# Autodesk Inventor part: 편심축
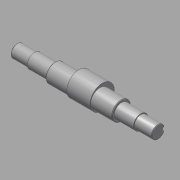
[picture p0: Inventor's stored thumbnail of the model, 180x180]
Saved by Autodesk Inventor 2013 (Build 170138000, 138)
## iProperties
Created: 2015-10
Part Number: 편심축
Document SubType Name: Modeling
Designer: mdu
Density: 1 g/cm^3
Material: 강철, 연강
Mass: 168.947 g
Surface Area: 248.524 cm^2
Volume: 168.947 cm^3
Author: mdu
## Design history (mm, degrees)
sketch "스케치1"
  geometry: L1 (-20.5, -41.331)-(-20.5, 32.669) reference; L2 (7.5, -30.031)-(7.5, 21.369) reference; L3 (135.5, -30.331)-(135.5, 21.669) reference; L4 (121.5, 21.369)-(121.5, -30.031) reference; L5 (184.5, -4.331)-(-57.5, -4.331); L6 (184.5, -4.331)-(184.5, 6.669); L7 (154.5, 8.169)-(121.5, 8.169); L8 (121.5, 8.169)-(121.5, 11.669); L9 (121.5, 11.669)-(7.5, 11.669); L10 (7.5, 11.669)-(7.5, 8.169); L11 (7.5, 8.169)-(-27.5, 8.169); L12 (-27.5, 8.169)-(-27.5, 6.669); L13 (-27.5, 6.669)-(-57.5, 6.669); L14 (-57.5, 6.669)-(-57.5, -4.331); L15 (154.5, 8.169)-(154.5, 6.669); L16 (154.5, 6.669)-(184.5, 6.669); C1 r 32.5 at (64.5, -4.331) reference; 1 further point
  constraints: 24 end point, 8 perpendicular, 5 point on line, 3 parallel, 2 collinear
  dimensions: "d1" = 25 diameter of L11 L5; "d2" = 32 diameter of L9 L5; "d3" = 22 diameter of L13 L5; "d4" = 35 distance of L10.end L11.end; "d5" = 30 distance of L12.end L13.end; "d15" = 33 distance of L7.start L7.end; "d26" = 30 distance of L15.end L6.end
revolve "회전1" sketch "스케치1" stored, may be unused: angle "d6" = 90 deg
node "작업 평면1"
sketch "스케치2"
  geometry: C1 r 16 at (0, 0) reference; C2 r 16 at (0, 0) reference; C3 r 20.75 at (0, 4); C4 r 16 at (0, 0) reference; 1 further point
  constraints: 1 centre point, 1 vertical alignment
  dimensions: "d8" = 41.5 diameter of C3; "d25" = 4 distance of C3.centre C1.centre
extrude "돌출1" join sketch "스케치2" stored distance "d9" = 40; taper "d10" = 0 deg
chamfer "모따기1" distance "d11" = 1; stored, may be unused: second distance "d12" = 2, angle "d13" = 45 deg
node "작업 평면2"
sketch "스케치3"
  geometry: L1 (-15, -10)-(-15, 10) reference; L2 (-15, 3)-(0, 3); L3 (0, -3)-(-15, -3); A1 r 3 centre (0, 0) between (0, -3) and (0, 3); 2 further points
  constraints: 4 end point, 2 perpendicular, 2 point on circle, 2 point on line, 2 tangent, 1 centre point, 1 horizontal alignment, 1 midpoint
  dimensions: "d16" = 18 dimension on A1 L1; "d17" = 6 distance between parallel lines of L3 L2
extrude "돌출2" cut sketch "스케치3" distance "d18" = 3.5; taper "d19" = 0 deg
node "작업 평면3"
node "솔리드1"
mirror "대칭1"
node "참조1"
node "참조2"
node "참조3"
node "참조4"
node "참조5"
node "투영된 루프1"
